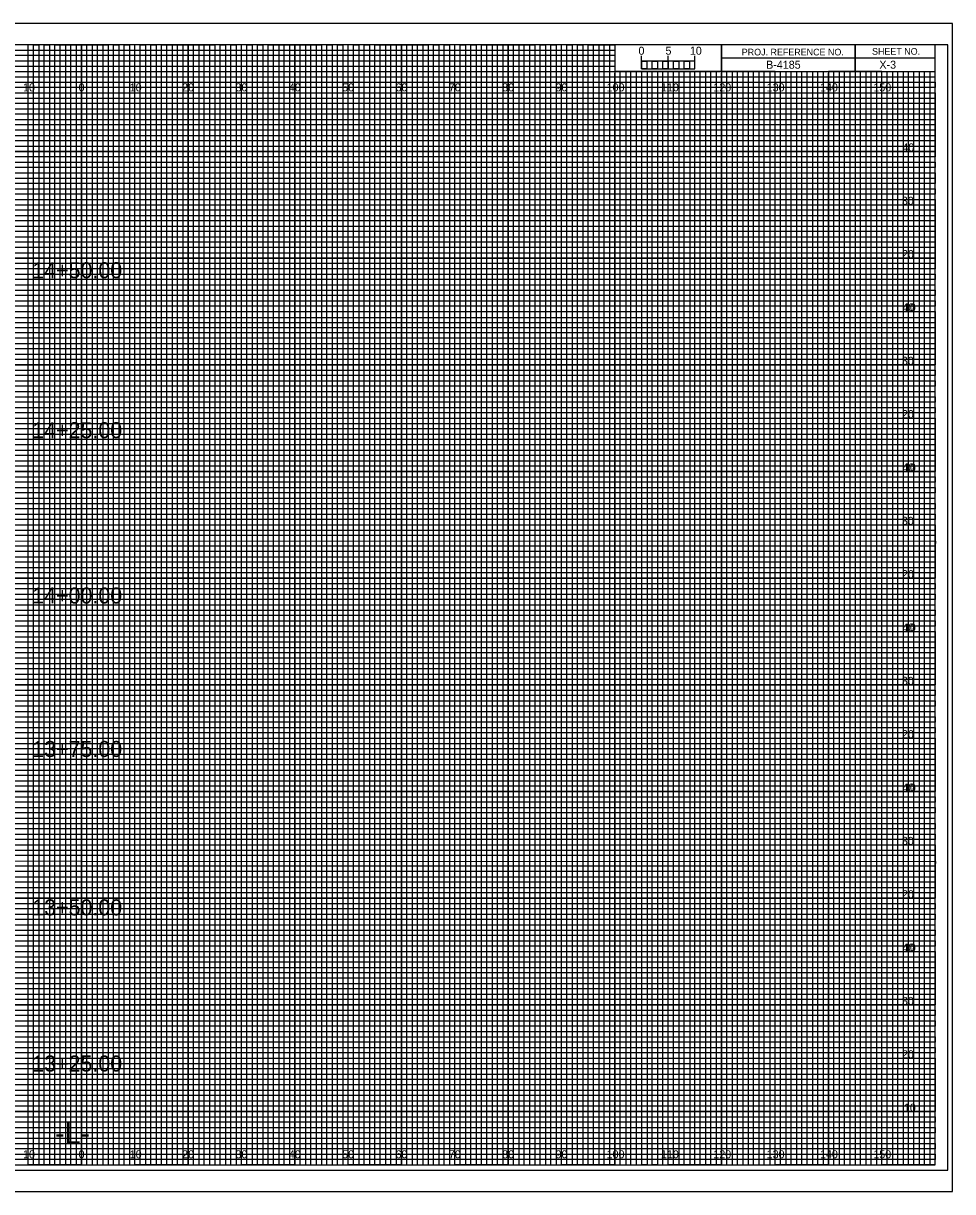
# Model space of a CAD drawing. Extents: x -13 to 323, y 215 to 434.
# Drawn here: x 149.1 to 323.3, y 215 to 434 of the extents above; entities that cross this region are included whole.
import ezdxf

# ---------------------------------------------------------------- set-up
doc = ezdxf.new("R2010")
doc.units = 0
for name, color, linetype in [('Prop XS Alignment Label', 7, 'Continuous'), ('Prop XS Bar Scale Labels', 7, 'Continuous'), ('Prop XS Elevation Labels', 7, 'Continuous'), ('Prop XS Offset Labels', 7, 'Continuous'), ('Prop XS Project Number', 7, 'Continuous'), ('Prop XS Sheet Number', 7, 'Continuous'), ('Prop XS Station Labels', 7, 'Continuous'), ('Sheet Cross Section CELL', 7, 'Continuous'), ('Sheet Cross Section Grid Major CELL', 7, 'Continuous'), ('Sheet Cross Section Grid Middle CELL', 7, 'Continuous'), ('Sheet Cross Section Grid Minor 1 CELL', 7, 'Continuous'), ('Sheet Cross Section Grid Minor 2 CELL', 7, 'Continuous'), ('Sheet Cross Section Scale CELL', 7, 'Continuous'), ('Sheet Cutting Line CELL', 7, 'Continuous'), ('Sheet DOT Grid CELL', 7, 'Continuous'), ('Sheet Plot Border Inside CELL', 7, 'Continuous'), ('Sheet Plot Border Outside CELL', 7, 'Continuous')]:
    doc.layers.add(name, color=color, linetype=linetype)

msp = doc.modelspace()

# ---------------------------------------------------------------- linework, layer by layer
at = {"layer": 'Sheet Cross Section CELL'}
for p, q in [((305, 430), (305, 425)), ((305, 425), (305, 430)), ((280, 427.5), (280, 425)), ((320, 427.49), (280, 427.49)), ((280, 425), (320, 425))]:
    msp.add_line(p, q, dxfattribs=at)
for points in [[(320, 430), (0, 430), (0, 220), (320, 220)], [(280, 430), (260, 430), (260, 425.03), (280, 425.03)], [(320, 430), (280, 430), (280, 425), (320, 425)]]:
    msp.add_lwpolyline(points, close=True, dxfattribs=at)
at = {"layer": 'Sheet Cross Section Grid Major CELL'}
for p, q in [((150, 430), (140, 430)), ((150, 220), (150, 430)), ((170, 430), (160, 430)), ((160, 430), (160, 220)), ((170, 220), (170, 430)), ((190, 430), (180, 430)), ((180, 430), (180, 220)), ((190, 220), (190, 430)), ((210, 430), (200, 430)), ((200, 430), (200, 220)), ((210, 220), (210, 430)), ((230, 430), (220, 430)), ((220, 430), (220, 220)), ((230, 220), (230, 430)), ((250, 430), (240, 430)), ((240, 430), (240, 220)), ((250, 220), (250, 430)), ((260, 430), (260, 220)), ((270, 220), (270, 425)), ((290, 425), (280, 425)), ((280, 425), (280, 220)), ((290, 220), (290, 425)), ((310, 425), (300, 425)), ((300, 425), (300, 220)), ((310, 220), (310, 425)), ((160, 220), (150, 220)), ((180, 220), (170, 220)), ((200, 220), (190, 220)), ((220, 220), (210, 220)), ((240, 220), (230, 220)), ((260, 220), (250, 220)), ((280, 220), (270, 220)), ((300, 220), (290, 220)), ((320, 220), (310, 220)), ((320, 220), (320, 220))]:
    msp.add_line(p, q, dxfattribs=at)
for points in [[(0, 420), (320, 420), (320, 410), (0, 410)], [(0, 400), (320, 400), (320, 390), (0, 390)], [(0, 380), (320, 380), (320, 370), (0, 370)], [(0, 360), (320, 360), (320, 350), (0, 350)], [(0, 340), (320, 340), (320, 330), (0, 330)], [(0, 320), (320, 320), (320, 310), (0, 310)], [(0, 300), (320, 300), (320, 290), (0, 290)], [(0, 280), (320, 280), (320, 270), (0, 270)], [(0, 260), (320, 260), (320, 250), (0, 250)], [(0, 240), (320, 240), (320, 230), (0, 230)]]:
    msp.add_lwpolyline(points, dxfattribs=at)
at = {"layer": 'Sheet Cross Section Grid Middle CELL'}
for points in [[(145, 220), (155, 220), (155, 430), (165, 430), (165, 220), (175, 220), (175, 430), (185, 430), (185, 220), (195, 220), (195, 430), (205, 430), (205, 220), (215, 220), (215, 430), (225, 430), (225, 220), (235, 220), (235, 430), (245, 430), (245, 220), (255, 220), (255, 430), (259.93, 430), (260, 430), (260, 425), (264.99, 425), (264.99, 220), (275, 220), (275, 425), (285, 425), (285, 220), (295, 220), (295, 425), (305, 425), (305, 220), (315, 220), (315, 425)], [(0, 425), (275, 425)], [(0, 405), (320, 405), (320, 415), (0, 415)], [(0, 385), (320, 385), (320, 395), (0, 395)], [(0, 365), (320, 365), (320, 375), (0, 375)], [(0, 345), (320, 345), (320, 355), (0, 355)], [(0, 325), (320, 325), (320, 335), (0, 335)], [(0, 305), (320, 305), (320, 315), (0, 315)], [(0, 285), (320, 285), (320, 295), (0, 295)], [(0, 265), (320, 265), (320, 275), (0, 275)], [(0, 245), (320, 245), (320, 255), (0, 255)], [(0, 225), (320, 225), (320, 235), (0, 235)]]:
    msp.add_lwpolyline(points, dxfattribs=at)
at = {"layer": 'Sheet Cross Section Grid Minor 1 CELL'}
for p, q in [((0, 429), (260, 429)), ((260, 427.98), (0, 427.98)), ((260, 429), (260, 427.98)), ((0, 427), (260, 427)), ((260, 425.89), (0, 425.89)), ((260, 427), (260, 425.89)), ((0, 424), (320, 424))]:
    msp.add_line(p, q, dxfattribs=at)
for points in [[(0, 423), (270, 423), (320, 423), (320, 422), (0, 422)], [(0, 421), (320, 421), (320, 419), (0, 419)], [(0, 418), (320, 418), (320, 417), (0, 416.98)], [(0, 416), (320, 416), (320, 414), (0, 414)], [(0, 413), (320, 413), (320, 412), (0, 412)], [(0, 411), (320, 411), (320, 409), (0, 409)], [(0, 408), (320, 408), (320, 407), (0, 407)], [(0, 406), (320, 406), (320, 404), (0, 404)], [(0, 403), (320, 403), (320, 402), (0, 402)], [(0, 401), (320, 401), (320, 399), (0, 399)], [(0, 398), (320, 398), (320, 397), (0, 397)], [(0, 396), (320, 396), (320, 393.95), (320, 393), (320, 392), (0, 392)], [(0, 394), (320, 394), (320, 393), (0, 393)], [(0, 391), (320, 391), (320, 389), (0, 389.03)], [(0, 389.03), (320, 389), (320, 388), (0, 388)], [(0, 387), (320, 387), (320, 386), (0, 386)], [(0, 384), (320, 384), (320, 383), (0, 383)], [(0, 382), (320, 382), (320, 381), (0, 381)], [(-0.07, 378.89), (320, 378.89), (320, 377.88), (-0.07, 377.88)], [(0, 377), (320, 377), (320, 376), (0, 376)], [(0, 374), (320, 374), (320, 373), (0, 373)], [(0, 372), (320, 372), (320, 371), (0, 371)], [(0, 369), (320, 369), (320, 368), (0, 368)], [(0, 367), (320, 367), (320, 366), (0, 366)], [(0, 364), (320, 364), (320, 363), (0, 363)], [(0, 362), (320, 362), (320, 361), (0, 361)], [(0, 359), (320, 359), (319.99, 357.98), (0, 358)], [(0, 357), (320, 357), (320, 356), (0, 356)], [(0, 354), (320, 354), (320, 353), (0, 353)], [(0, 352), (320, 352), (320, 351), (0, 351)], [(0, 349), (320, 349), (320, 348), (0, 348)], [(0, 347), (320, 347), (320, 346), (0, 346)], [(0, 344), (320, 344), (320, 343), (0, 343)], [(0, 342), (320, 342), (320, 341), (0, 341)], [(0, 339), (320, 339), (320, 338), (0, 338)], [(0, 336.99), (320.07, 336.91), (320, 336), (0, 336)], [(0, 334), (320, 334), (320, 333), (0, 333)], [(0, 332), (320, 332), (320, 331), (0, 331)], [(0, 329), (320, 329), (320, 328), (0, 328)], [(0, 327), (320, 327), (320, 326), (0, 326)], [(0, 324), (320, 324), (320, 323), (0, 323)], [(0, 322), (320, 322), (320, 321), (0, 321)], [(0, 319), (320, 319), (320, 318), (0, 318)], [(0, 317), (320, 317), (320, 316), (0, 316)], [(0, 314), (320, 314), (320, 313), (0, 313)], [(0, 312), (320, 312), (320, 311), (0, 311)], [(0, 309), (320, 309), (320, 308), (0, 308)], [(0, 307), (320, 307), (320, 306), (0, 306)], [(0, 304), (320, 304), (320, 303), (0, 303)], [(0, 302), (320, 302), (320, 301), (0, 301)], [(0, 299), (320, 299), (319.99, 297.98), (0, 298)], [(0, 297), (320, 297), (320, 296), (0, 296)], [(0, 294), (320, 294), (320, 293), (0, 293)], [(0, 292), (320, 292), (320, 291), (0, 291)], [(0, 289), (320, 289), (320, 288), (0, 288)], [(0, 287), (320, 287), (320, 286), (0, 286)], [(0, 284), (320, 284), (320, 283), (0, 283)], [(0, 282), (320, 282), (320, 281), (0, 281)], [(0, 279), (320, 279), (320, 278), (0, 278)], [(0, 276.99), (320.07, 276.91), (320, 276), (0, 276)], [(0, 274), (320, 274), (320, 273), (0, 273)], [(0, 272), (320, 272), (320, 271), (0, 271)], [(0, 269), (320, 269), (320, 268), (0, 268)], [(0, 267), (320, 267), (320, 266), (0, 266)], [(0, 264), (320, 264), (320, 263), (0, 263)], [(0, 262), (320, 262), (320, 261), (0, 261)], [(0, 259), (320, 259), (320, 258), (0, 258)], [(0, 257), (320, 257), (320, 256), (0, 256)], [(0, 254), (320, 254), (320, 253), (0, 253)], [(0, 252), (320, 252), (320, 251), (0, 251)], [(0, 249), (320, 249), (320, 248), (0, 248)], [(0, 247), (320, 247), (320, 246), (0, 246)], [(0, 244), (320, 244), (320, 243), (0, 243)], [(0, 242), (320, 242), (320, 241), (0, 241)], [(0, 239), (320, 239), (320, 238), (0, 238)], [(0, 237), (320, 237), (320, 236), (0, 236)], [(0, 234), (320, 234), (320, 233), (0, 233)], [(0, 232), (320, 232), (320, 231), (0, 231)], [(0, 229), (320, 229), (320, 228), (0, 228)], [(0, 227), (320, 227), (320, 226), (0, 226)], [(0, 224), (320, 224), (320, 223), (0, 223)], [(0, 222), (320, 222), (320, 221), (0, 221)]]:
    msp.add_lwpolyline(points, dxfattribs=at)
at = {"layer": 'Sheet Cross Section Grid Minor 2 CELL'}
for p, q in [((267, 425), (266.01, 425)), ((266.01, 425), (266.01, 220)), ((267, 220), (267, 425)), ((269, 425), (268, 425)), ((268, 425), (268, 220)), ((269, 220), (269, 425)), ((266.01, 220), (265, 220)), ((268, 220), (267, 220))]:
    msp.add_line(p, q, dxfattribs=at)
for points in [[(150, 220), (151, 220), (151, 430), (152, 430), (152, 220)], [(152, 220), (153, 220), (153, 430), (154, 430), (154, 220)], [(155, 220), (156, 220), (156, 430), (157, 430), (157, 220)], [(157, 220), (158, 220), (158, 430), (159, 430), (159, 220)], [(160, 220), (161, 220), (161, 430), (162, 430), (162, 220)], [(162, 220), (163, 220), (163, 430), (164, 430), (164, 220)], [(165, 220), (166, 220), (166, 430), (167, 430), (167, 220)], [(167, 220), (168, 220), (168, 430), (169, 430), (169, 220)], [(170, 220), (171, 220), (171, 430), (172, 430), (172, 220)], [(172, 220), (173, 220), (173, 430), (174, 430), (174, 220)], [(175, 220), (176, 220), (176, 430), (177, 430), (177, 220)], [(177, 220), (178, 220), (178, 430), (179, 430), (179, 220)], [(180, 220), (181, 220), (181, 430), (182, 430), (182, 220)], [(182, 220), (183, 220), (183, 430), (184, 430), (184, 220)], [(185, 220), (186, 220), (186, 430), (187, 430), (187, 220)], [(187, 220), (188, 220), (188, 430), (189, 430), (189, 220)], [(190, 220), (191, 220), (191, 430), (192, 430), (192, 220)], [(192, 220), (193, 220), (193, 430), (194, 430), (194, 220)], [(195, 220), (196, 220), (196, 430), (197, 430), (197, 220)], [(197, 220), (198, 220), (198, 430), (199, 430), (199, 220)], [(200, 220), (201, 220), (201, 430), (202, 430), (202, 220)], [(202, 220), (203, 220), (203, 430), (204, 430), (204, 220)], [(205, 220), (206, 220), (206, 430), (207, 430), (207, 220)], [(207, 220), (208, 220), (208, 430), (209, 430), (209, 220)], [(210, 220), (211, 220), (211, 430), (212, 430), (212, 220)], [(212, 220), (213, 220), (213, 430), (214, 430), (214, 220)], [(215, 220), (216, 220), (216, 430), (217, 430), (217, 220)], [(217, 220), (218, 220), (218, 430), (219, 430), (219, 220)], [(220, 220), (221, 220), (221, 430), (222, 430), (222, 220)], [(222, 220), (223, 220), (223, 430), (224, 430), (224, 220)], [(225, 220), (226, 220), (226, 430), (227, 430), (227, 220)], [(227, 220), (228, 220), (228, 430), (229, 430), (229, 220)], [(230, 220), (231, 220), (231, 430), (232, 430), (232, 220)], [(232, 220), (233, 220), (233, 430), (234, 430), (234, 220)], [(235, 220), (236, 220), (236, 430), (237, 430), (237, 220)], [(237, 220), (238, 220), (238, 430), (239, 430), (239, 220)], [(240, 220), (241, 220), (241, 430), (242, 430), (242, 220)], [(242, 220), (243, 220), (243, 430), (244, 430), (244, 220)], [(245, 220), (246, 220), (246, 430), (247, 430), (247, 220)], [(247, 220), (248, 220), (248, 430), (249, 430), (249, 220)], [(250, 220), (251, 220), (251, 430), (252, 430), (252, 220)], [(252, 220), (253, 220), (253, 430), (254, 430), (254, 220)], [(255, 220), (256, 220), (256, 430), (257, 430), (257, 220)], [(257, 220), (258, 220), (258, 430), (259, 430), (259, 220)], [(260, 220), (261, 220), (261, 425), (262.02, 425), (262.02, 220)], [(262, 220), (263, 220), (263, 425), (263.99, 425), (263.99, 220)], [(270, 220), (270.98, 220), (270.98, 425), (272, 425), (272, 220)], [(272, 220), (273, 220), (273, 425), (274.05, 425), (274.05, 220)], [(275, 220), (276, 220), (276, 425), (277, 425), (277, 220)], [(277, 220), (278, 220), (278, 425), (279, 425), (279, 220)], [(280, 220), (281, 220), (281, 425), (282, 425), (282, 220)], [(282, 220), (283, 220), (283, 425), (284, 425), (284, 220)], [(285, 220), (286, 220), (286, 425), (287, 425), (287, 220)], [(287, 220), (288, 220), (288, 425), (289, 425), (289, 220)], [(290, 220), (291, 220), (291, 425), (292, 425), (292, 220)], [(292, 220), (293, 220), (293, 425), (294, 425), (294, 220)], [(295, 220), (296, 220), (296, 425), (297, 425), (297, 220)], [(297, 220), (298, 220), (298, 425), (299, 425), (299, 220)], [(300, 220), (301, 220), (301, 425), (302, 425), (302, 220)], [(302, 220), (303, 220), (303, 425), (304, 425), (304, 220)], [(305, 220), (306, 220), (306, 425), (307, 425), (307, 220)], [(307, 220), (308, 220), (308, 425), (309, 425), (309, 220)], [(310, 220), (311, 220), (311, 425), (312, 425), (312, 220)], [(312, 220), (313, 220), (313, 425), (314, 425), (314, 220)], [(315, 220), (316, 220), (316, 425), (317, 425), (317, 220)], [(317, 220), (318, 220), (318, 425), (319, 425), (319, 220)]]:
    msp.add_lwpolyline(points, dxfattribs=at)
at = {"layer": 'Sheet Cross Section Scale CELL'}
for p, q in [((265, 425.49), (265, 427.9)), ((265, 426.9), (265, 427.9)), ((270, 425.49), (270, 427.9)), ((275, 425.49), (275, 427.9)), ((275, 426.9), (275, 427.9))]:
    msp.add_line(p, q, dxfattribs=at)
for points in [[(275, 426.9), (265, 426.9), (265, 425.49), (275, 425.49)], [(265, 426.9), (266, 426.9), (266, 425.49), (265, 425.49)], [(267, 426.9), (268, 426.9), (268, 425.49), (267, 425.49)], [(269, 426.9), (270, 426.9), (270, 425.49), (269, 425.49)], [(271, 426.9), (272, 426.9), (272, 425.49), (271, 425.49)], [(273, 426.9), (274, 426.9), (274, 425.49), (273, 425.49)]]:
    msp.add_lwpolyline(points, close=True, dxfattribs=at)
at = {"layer": 'Sheet Cutting Line CELL'}
for p, q in [((323.3, 434), (-13.4, 434)), ((-13.4, 215), (323.3, 215))]:
    msp.add_line(p, q, dxfattribs=at)
at = {"layer": 'Sheet DOT Grid CELL'}
for p, q in [((150, 220), (150, 430)), ((160, 220), (160, 430)), ((170, 220), (170, 430)), ((180, 220), (180, 430)), ((190, 220), (190, 430)), ((200, 220), (200, 430)), ((210, 220), (210, 430)), ((220, 220), (220, 430)), ((230, 220), (230, 430)), ((240, 220), (240, 430)), ((250, 220), (250, 430)), ((260, 220), (260, 424.69)), ((270, 220), (270, 424.69)), ((280, 220), (280, 424.69)), ((290, 220), (290, 424.69)), ((300, 220), (300, 424.69)), ((310, 220), (310, 424.69)), ((0, 420), (320, 420)), ((0, 410), (320, 410)), ((0, 400), (320, 400)), ((0, 390), (320, 390)), ((0, 380), (320, 380)), ((0, 370), (320, 370)), ((0, 360), (320, 360)), ((0, 350), (320, 350)), ((0, 340), (320, 340)), ((0, 330), (320, 330)), ((0, 320), (320, 320)), ((0, 310), (320, 310)), ((0, 300), (320, 300)), ((0, 290), (320, 290)), ((0, 280), (320, 280)), ((0, 270), (320, 270)), ((0, 260), (320, 260)), ((0, 250), (320, 250)), ((0, 240), (320, 240)), ((0, 230), (320, 230))]:
    msp.add_line(p, q, dxfattribs=at)
at = {"layer": 'Sheet Plot Border Inside CELL'}
msp.add_lwpolyline([(-10.8, 219), (322.4, 219), (322.4, 430), (-10.8, 430)], close=True, dxfattribs=at)
at = {"layer": 'Sheet Plot Border Outside CELL'}
msp.add_lwpolyline([(-13.4, 215), (323.3, 215), (323.3, 434), (-13.4, 434)], close=True, dxfattribs=at)

# ---------------------------------------------------------------- texts
at = {"layer": 'Prop XS Alignment Label'}
msp.add_text('-L-', height=4, dxfattribs=at).set_placement((155.06, 224))
at = {"layer": 'Prop XS Bar Scale Labels'}
for s, p in [('5', (269.47, 428.12)), ('10', (274.04, 428.12))]:
    msp.add_text(s, height=1.5, dxfattribs=at).set_placement(p)
at = {"layer": 'Prop XS Elevation Labels'}
for s, p in [('40', (313.87, 410)), ('30', (313.78, 400)), ('20', (313.8, 390)), ('40', (313.87, 380)), ('10', (314.17, 380)), ('30', (313.78, 370)), ('20', (313.8, 360)), ('40', (313.87, 350)), ('10', (314.17, 350)), ('30', (313.78, 340)), ('20', (313.8, 330)), ('40', (313.87, 320)), ('10', (314.17, 320)), ('30', (313.78, 310)), ('20', (313.8, 300)), ('40', (313.87, 290)), ('10', (314.17, 290)), ('30', (313.78, 280)), ('20', (313.8, 270)), ('40', (313.87, 260)), ('10', (314.17, 260)), ('30', (313.78, 250)), ('20', (313.8, 240)), ('10', (314.17, 230))]:
    msp.add_text(s, height=1.5, dxfattribs=at).set_placement(p)
at = {"layer": 'Prop XS Offset Labels'}
for s, p in [('10', (149.04, 421.25)), ('0', (159.45, 421.25)), ('0', (159.45, 421.25)), ('10', (169.04, 421.25)), ('20', (178.86, 421.25)), ('30', (188.86, 421.25)), ('40', (198.86, 421.25)), ('50', (208.86, 421.25)), ('60', (218.86, 421.25)), ('70', (228.86, 421.25)), ('80', (238.86, 421.25)), ('90', (248.86, 421.25)), ('100', (258.44, 421.25)), ('110', (268.62, 421.25)), ('120', (278.44, 421.25)), ('130', (288.44, 421.25)), ('140', (298.44, 421.25)), ('150', (308.44, 421.25)), ('10', (149.04, 221.25)), ('0', (159.45, 221.25)), ('0', (159.45, 221.25)), ('10', (169.04, 221.25)), ('20', (178.86, 221.25)), ('30', (188.86, 221.25)), ('40', (198.86, 221.25)), ('50', (208.86, 221.25)), ('60', (218.86, 221.25)), ('70', (228.86, 221.25)), ('80', (238.86, 221.25)), ('90', (248.86, 221.25)), ('100', (258.44, 221.25)), ('110', (268.62, 221.25)), ('120', (278.44, 221.25)), ('130', (288.44, 221.25)), ('140', (298.44, 221.25)), ('150', (308.44, 221.25))]:
    msp.add_text(s, height=1.5, dxfattribs=at).set_placement(p)
at = {"layer": 'Prop XS Project Number'}
msp.add_text('B-4185', height=1.5, dxfattribs=at).set_placement((288.34, 425.5))
at = {"layer": 'Prop XS Sheet Number'}
msp.add_text('X-3', height=1.5, dxfattribs=at).set_placement((309.57, 425.5))
at = {"layer": 'Prop XS Station Labels'}
for s, p in [('14+50.00', (150.77, 386.22)), ('14+25.00', (150.77, 356.24)), ('14+00.00', (150.77, 325.25)), ('13+75.00', (150.77, 296.48)), ('13+50.00', (150.77, 266.79)), ('13+25.00', (150.77, 237.52))]:
    msp.add_text(s, height=3, dxfattribs=at).set_placement(p)
at = {"layer": 'Sheet Cross Section CELL'}
for s, p in [('PROJ. REFERENCE NO.', (283.77, 427.99)), ('SHEET NO.', (308.19, 428.12))]:
    msp.add_text(s, height=1.25, dxfattribs=at).set_placement(p)
at = {"layer": 'Sheet Cross Section Scale CELL'}
msp.add_text('0', height=1.5, dxfattribs=at).set_placement((264.41, 428.12))

doc.saveas('drawing.dxf')
